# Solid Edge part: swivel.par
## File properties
Title: Swivel
Author: Deepak Maini
Template: normal.par
Last saved by: Robert a Rhodes jr
Revision: 11
Application: Solid Edge
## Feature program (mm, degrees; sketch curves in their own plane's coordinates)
sketch for "unnamed RevolvedProtrusion 1" plane through (0, 0, -25.4) normal (0, 0, 1) x-axis (1, 0, 0)
revolve "unnamed RevolvedProtrusion 1" add finite 360 deg about sketch line (-85.0097, -12.7562) -> (-3.81, -12.7562)
sketch for "unnamed RevolvedProtrusion 2" plane through (0, -12.7, 0) normal (0, -1, 0) x-axis (1, 0, 0)
revolve "unnamed RevolvedProtrusion 2" add full turn 360 deg about sketch line (-44.45, 28.0428) -> (-44.45, -71.2043)
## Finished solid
Body 1: solid body, 14 faces, 13 edges, 0 vertices.
  Faces by surface: plane 8, cylinder 6
  Edges by curve: circle 12, intersection 1
Bounding box of the edges (mm): 81.200 x 25.456 x 81.280, from (-85.0097, -25.4562, -66.04) to (-3.81, 0, 15.24).
Cylindrical faces by radius (mm): R6.35 x4, R12.7 x2
Planar faces by outward normal: +x 2, +z 2, -x 2, -z 2
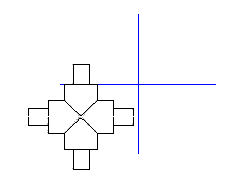
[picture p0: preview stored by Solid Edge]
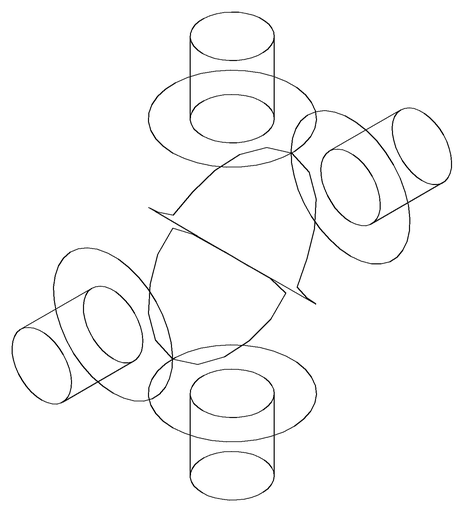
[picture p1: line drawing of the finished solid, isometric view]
